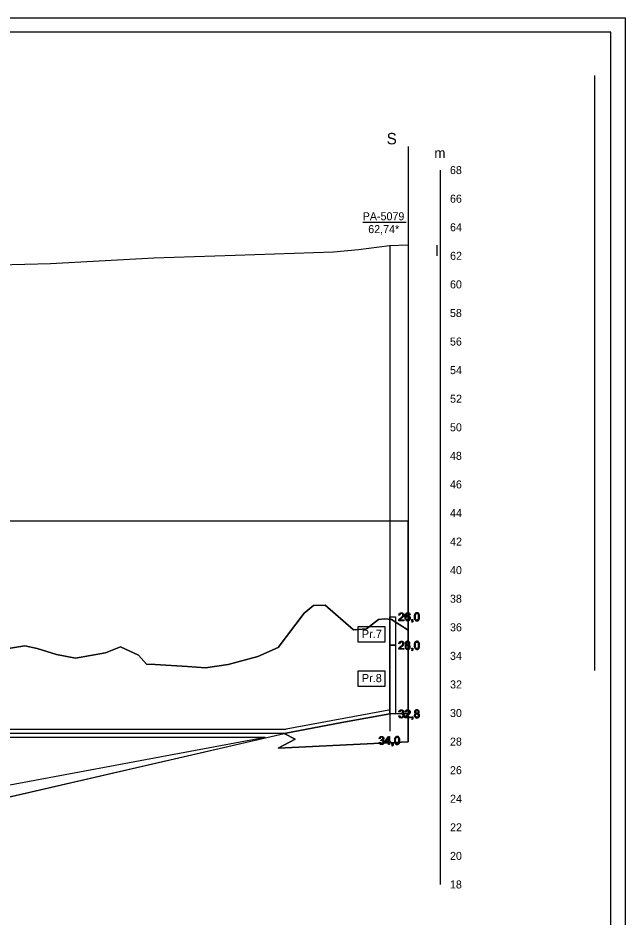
# Model space of a CAD drawing. Extents: x 700746 to 706058, y 6570320 to 6580460.
# Drawn here: x 705472 to 705897, y 6574741 to 6575370 of the extents above; entities that cross this region are included whole.
import ezdxf

# ---------------------------------------------------------------- set-up
doc = ezdxf.new("R2010")
doc.units = 0
for name, color, linetype in [('ABIJOONIS', 7, 'Continuous'), ('GEOLPUNKT', 7, 'Continuous'), ('GEOLPUNKT_proovid', 7, 'Continuous'), ('Lõige', 7, 'Continuous'), ('Lõige vormistus', 7, 'Continuous'), ('Maapind', 7, 'Continuous'), ('PIIR', 7, 'Continuous'), ('Plokid', 7, 'Continuous'), ('Täide', 7, 'Continuous'), ('VEEKOGU', 7, 'Continuous'), ('Veetase', 7, 'Continuous'), ('VORMISTUS', 7, 'Continuous')]:
    doc.layers.add(name, color=color, linetype=linetype)

msp = doc.modelspace()

# ---------------------------------------------------------------- linework, layer by layer
at = {"layer": 'ABIJOONIS'}
msp.add_lwpolyline([(704017.06, 6575370.2), (705897.06, 6575370.2), (705897.06, 6574500.2), (704017.06, 6574500.2), (704017.06, 6575370.2)], dxfattribs=at)
at = {"layer": 'GEOLPUNKT'}
for p, q in [((705713.48, 6575227.4), (705743.92, 6575227.4)), ((705732.33, 6575211.13), (705732.33, 6574949.04)), ((705732.33, 6574949.04), (705732.33, 6574871.13))]:
    msp.add_line(p, q, dxfattribs=at)
at = {"layer": 'GEOLPUNKT_proovid'}
for points in [[(705732.33, 6574951.13), (705736.33, 6574951.13), (705736.33, 6574931.13), (705732.33, 6574931.13)], [(705710.25, 6574944.24), (705728.96, 6574944.24), (705728.96, 6574933.28), (705710.25, 6574933.28)], [(705732.33, 6574931.13), (705736.33, 6574931.13), (705736.33, 6574883.13), (705732.33, 6574883.13)], [(705710.25, 6574913.31), (705728.96, 6574913.31), (705728.96, 6574902.35), (705710.25, 6574902.35)]]:
    msp.add_lwpolyline(points, close=True, dxfattribs=at)
for points in [[(705739.45, 6574952.26), (705738.74, 6574952.33)], [(705746.62, 6574952.55), (705745.94, 6574952.5)], [(705742.31, 6574948.99), (705742.31, 6574948.33), (705738.61, 6574948.33)], [(705739.57, 6574948.99), (705742.31, 6574948.99)], [(705747.91, 6574947.22), (705747.72, 6574947.51)], [(705747.77, 6574948.33), (705747.77, 6574949.11), (705748.55, 6574949.11), (705748.55, 6574948.33)], [(705748.16, 6574948.33), (705747.77, 6574948.33)], [(705739.45, 6574932.26), (705738.74, 6574932.33)], [(705742.31, 6574928.99), (705742.31, 6574928.33), (705738.61, 6574928.33)], [(705739.57, 6574928.99), (705742.31, 6574928.99)], [(705747.91, 6574927.22), (705747.72, 6574927.51)], [(705747.77, 6574928.33), (705747.77, 6574929.11), (705748.55, 6574929.11), (705748.55, 6574928.33)], [(705748.16, 6574928.33), (705747.77, 6574928.33)], [(705738.7, 6574881.81), (705739.39, 6574881.9)], [(705739.46, 6574884.38), (705738.77, 6574884.5)], [(705740.06, 6574882.98), (705740.14, 6574883.59)], [(705743.8, 6574884.26), (705743.09, 6574884.33)], [(705746.66, 6574880.99), (705746.66, 6574880.33), (705742.96, 6574880.33)], [(705743.92, 6574880.99), (705746.66, 6574880.99)], [(705747.91, 6574879.22), (705747.72, 6574879.51)], [(705747.77, 6574880.33), (705747.77, 6574881.11), (705748.55, 6574881.11), (705748.55, 6574880.33)], [(705748.16, 6574880.33), (705747.77, 6574880.33)]]:
    msp.add_lwpolyline(points, dxfattribs=at)
for points in [[(705738.61, 6574948.33), (705738.6, 6574948.58), (705738.69, 6574948.81), (705738.83, 6574949.19), (705739.14, 6574949.55), (705739.45, 6574949.92), (705740.04, 6574950.4), (705740.95, 6574951.15), (705741.27, 6574951.59), (705741.59, 6574952.02), (705741.59, 6574952.41), (705741.59, 6574952.82), (705741.3, 6574953.1), (705741.01, 6574953.38), (705740.54, 6574953.38), (705740.05, 6574953.38), (705739.75, 6574953.08), (705739.45, 6574952.79), (705739.45, 6574952.26)], [(705738.74, 6574952.33), (705738.81, 6574953.12), (705739.28, 6574953.54), (705739.76, 6574953.95), (705740.56, 6574953.95), (705741.36, 6574953.95), (705741.83, 6574953.5), (705742.3, 6574953.06), (705742.3, 6574952.4), (705742.3, 6574952.06), (705742.16, 6574951.74), (705742.03, 6574951.41), (705741.71, 6574951.05), (705741.39, 6574950.69), (705740.65, 6574950.07), (705740.03, 6574949.55), (705739.86, 6574949.36), (705739.68, 6574949.18), (705739.57, 6574948.99)], [(705745.94, 6574952.5), (705745.85, 6574952.91), (705745.68, 6574953.09), (705745.4, 6574953.39), (705744.99, 6574953.39), (705744.66, 6574953.39), (705744.41, 6574953.2), (705744.08, 6574952.97), (705743.9, 6574952.51), (705743.71, 6574952.06), (705743.7, 6574951.22), (705743.95, 6574951.59), (705744.31, 6574951.78), (705744.67, 6574951.96), (705745.06, 6574951.96), (705745.75, 6574951.96), (705746.24, 6574951.46), (705746.72, 6574950.95), (705746.72, 6574950.15), (705746.72, 6574949.62), (705746.49, 6574949.17), (705746.26, 6574948.72), (705745.87, 6574948.48), (705745.47, 6574948.24), (705744.96, 6574948.24), (705744.1, 6574948.24), (705743.56, 6574948.87), (705743.02, 6574949.5), (705743.02, 6574950.95), (705743.02, 6574952.57), (705743.62, 6574953.31), (705744.14, 6574953.95), (705745.03, 6574953.95), (705745.69, 6574953.95), (705746.11, 6574953.58), (705746.54, 6574953.21), (705746.62, 6574952.55)], [(705743.81, 6574950.14), (705743.81, 6574949.79), (705743.96, 6574949.46), (705744.11, 6574949.14), (705744.38, 6574948.97), (705744.65, 6574948.8), (705744.95, 6574948.8), (705745.39, 6574948.8), (705745.7, 6574949.15), (705746.01, 6574949.5), (705746.01, 6574950.11), (705746.01, 6574950.69), (705745.7, 6574951.02), (705745.39, 6574951.36), (705744.92, 6574951.36), (705744.46, 6574951.36), (705744.13, 6574951.02), (705743.81, 6574950.69), (705743.81, 6574950.14)], [(705749.57, 6574951.09), (705749.57, 6574952.08), (705749.78, 6574952.69), (705749.98, 6574953.3), (705750.38, 6574953.62), (705750.78, 6574953.95), (705751.4, 6574953.95), (705751.85, 6574953.95), (705752.19, 6574953.77), (705752.53, 6574953.59), (705752.75, 6574953.25), (705752.97, 6574952.9), (705753.09, 6574952.41), (705753.22, 6574951.92), (705753.22, 6574951.09), (705753.22, 6574950.11), (705753.02, 6574949.5), (705752.82, 6574948.89), (705752.41, 6574948.56), (705752.01, 6574948.24), (705751.4, 6574948.24), (705750.59, 6574948.24), (705750.12, 6574948.81), (705749.57, 6574949.51), (705749.57, 6574951.09)], [(705750.28, 6574951.09), (705750.28, 6574949.71), (705750.6, 6574949.25), (705750.92, 6574948.8), (705751.4, 6574948.8), (705751.87, 6574948.8), (705752.19, 6574949.26), (705752.51, 6574949.71), (705752.51, 6574951.09), (705752.51, 6574952.47), (705752.19, 6574952.93), (705751.87, 6574953.38), (705751.39, 6574953.38), (705750.92, 6574953.38), (705750.63, 6574952.98), (705750.28, 6574952.47), (705750.28, 6574951.09)], [(705747.72, 6574947.51), (705747.94, 6574947.61), (705748.04, 6574947.8), (705748.15, 6574947.98), (705748.16, 6574948.33)], [(705748.55, 6574948.33), (705748.55, 6574947.9), (705748.4, 6574947.63), (705748.25, 6574947.36), (705747.91, 6574947.22)], [(705738.61, 6574928.33), (705738.6, 6574928.58), (705738.69, 6574928.81), (705738.83, 6574929.19), (705739.14, 6574929.55), (705739.45, 6574929.92), (705740.04, 6574930.4), (705740.95, 6574931.15), (705741.27, 6574931.59), (705741.59, 6574932.02), (705741.59, 6574932.41), (705741.59, 6574932.82), (705741.3, 6574933.1), (705741.01, 6574933.38), (705740.54, 6574933.38), (705740.05, 6574933.38), (705739.75, 6574933.08), (705739.45, 6574932.79), (705739.45, 6574932.26)], [(705738.74, 6574932.33), (705738.81, 6574933.12), (705739.28, 6574933.54), (705739.76, 6574933.95), (705740.56, 6574933.95), (705741.36, 6574933.95), (705741.83, 6574933.5), (705742.3, 6574933.06), (705742.3, 6574932.4), (705742.3, 6574932.06), (705742.16, 6574931.74), (705742.03, 6574931.41), (705741.71, 6574931.05), (705741.39, 6574930.69), (705740.65, 6574930.07), (705740.03, 6574929.55), (705739.86, 6574929.36), (705739.68, 6574929.18), (705739.57, 6574928.99)], [(705744.11, 6574931.37), (705743.68, 6574931.52), (705743.47, 6574931.81), (705743.27, 6574932.1), (705743.27, 6574932.51), (705743.27, 6574933.12), (705743.71, 6574933.53), (705744.14, 6574933.95), (705744.87, 6574933.95), (705745.6, 6574933.95), (705746.05, 6574933.53), (705746.5, 6574933.1), (705746.5, 6574932.49), (705746.5, 6574932.1), (705746.29, 6574931.81), (705746.09, 6574931.52), (705745.67, 6574931.37), (705746.19, 6574931.2), (705746.46, 6574930.83), (705746.73, 6574930.45), (705746.73, 6574929.93), (705746.73, 6574929.21), (705746.22, 6574928.72), (705745.71, 6574928.24), (705744.88, 6574928.24), (705744.06, 6574928.24), (705743.55, 6574928.73), (705743.04, 6574929.22), (705743.04, 6574929.95), (705743.04, 6574930.5), (705743.32, 6574930.87), (705743.6, 6574931.23), (705744.11, 6574931.37)], [(705743.98, 6574932.53), (705743.98, 6574932.14), (705744.23, 6574931.88), (705744.48, 6574931.63), (705744.89, 6574931.63), (705745.29, 6574931.63), (705745.54, 6574931.88), (705745.79, 6574932.13), (705745.79, 6574932.49), (705745.79, 6574932.87), (705745.53, 6574933.13), (705745.27, 6574933.39), (705744.88, 6574933.39), (705744.49, 6574933.39), (705744.23, 6574933.14), (705743.98, 6574932.88), (705743.98, 6574932.53)], [(705749.57, 6574931.09), (705749.57, 6574932.08), (705749.78, 6574932.69), (705749.98, 6574933.3), (705750.38, 6574933.62), (705750.78, 6574933.95), (705751.4, 6574933.95), (705751.85, 6574933.95), (705752.19, 6574933.77), (705752.53, 6574933.59), (705752.75, 6574933.25), (705752.97, 6574932.9), (705753.09, 6574932.41), (705753.22, 6574931.92), (705753.22, 6574931.09), (705753.22, 6574930.11), (705753.02, 6574929.5), (705752.82, 6574928.89), (705752.41, 6574928.56), (705752.01, 6574928.24), (705751.4, 6574928.24), (705750.59, 6574928.24), (705750.12, 6574928.81), (705749.57, 6574929.51), (705749.57, 6574931.09)], [(705750.28, 6574931.09), (705750.28, 6574929.71), (705750.6, 6574929.25), (705750.92, 6574928.8), (705751.4, 6574928.8), (705751.87, 6574928.8), (705752.19, 6574929.26), (705752.51, 6574929.71), (705752.51, 6574931.09), (705752.51, 6574932.47), (705752.19, 6574932.93), (705751.87, 6574933.38), (705751.39, 6574933.38), (705750.92, 6574933.38), (705750.63, 6574932.98), (705750.28, 6574932.47), (705750.28, 6574931.09)], [(705743.75, 6574929.95), (705743.75, 6574929.65), (705743.89, 6574929.38), (705744.02, 6574929.1), (705744.3, 6574928.95), (705744.57, 6574928.8), (705744.89, 6574928.8), (705745.38, 6574928.8), (705745.7, 6574929.12), (705746.02, 6574929.43), (705746.02, 6574929.92), (705746.02, 6574930.42), (705745.69, 6574930.74), (705745.36, 6574931.07), (705744.87, 6574931.07), (705744.38, 6574931.07), (705744.07, 6574930.75), (705743.75, 6574930.43), (705743.75, 6574929.95)], [(705747.72, 6574927.51), (705747.94, 6574927.61), (705748.04, 6574927.8), (705748.15, 6574927.98), (705748.16, 6574928.33)], [(705748.55, 6574928.33), (705748.55, 6574927.9), (705748.4, 6574927.63), (705748.25, 6574927.36), (705747.91, 6574927.22)], [(705738.77, 6574884.5), (705738.9, 6574885.19), (705739.35, 6574885.57), (705739.79, 6574885.95), (705740.46, 6574885.95), (705740.92, 6574885.95), (705741.3, 6574885.75), (705741.69, 6574885.56), (705741.89, 6574885.22), (705742.1, 6574884.88), (705742.1, 6574884.5), (705742.1, 6574884.14), (705741.9, 6574883.84), (705741.71, 6574883.54), (705741.33, 6574883.36), (705741.82, 6574883.25), (705742.1, 6574882.89), (705742.37, 6574882.53), (705742.37, 6574881.99), (705742.37, 6574881.25), (705741.84, 6574880.74), (705741.3, 6574880.24), (705740.48, 6574880.24), (705739.75, 6574880.24), (705739.26, 6574880.67), (705738.77, 6574881.11), (705738.7, 6574881.81)], [(705739.39, 6574881.9), (705739.51, 6574881.32), (705739.79, 6574881.06), (705740.08, 6574880.8), (705740.49, 6574880.8), (705740.97, 6574880.8), (705741.31, 6574881.14), (705741.64, 6574881.47), (705741.64, 6574881.97), (705741.64, 6574882.45), (705741.33, 6574882.75), (705741.02, 6574883.06), (705740.54, 6574883.06), (705740.35, 6574883.06), (705740.06, 6574882.98)], [(705740.14, 6574883.59), (705740.2, 6574883.58), (705740.25, 6574883.58), (705740.69, 6574883.58), (705741.04, 6574883.81), (705741.39, 6574884.04), (705741.39, 6574884.51), (705741.39, 6574884.89), (705741.13, 6574885.14), (705740.88, 6574885.39), (705740.47, 6574885.39), (705740.07, 6574885.39), (705739.8, 6574885.13), (705739.54, 6574884.88), (705739.46, 6574884.38)], [(705742.96, 6574880.33), (705742.95, 6574880.58), (705743.04, 6574880.81), (705743.18, 6574881.19), (705743.49, 6574881.55), (705743.8, 6574881.92), (705744.39, 6574882.4), (705745.3, 6574883.15), (705745.62, 6574883.59), (705745.94, 6574884.02), (705745.94, 6574884.41), (705745.94, 6574884.82), (705745.65, 6574885.1), (705745.36, 6574885.38), (705744.89, 6574885.38), (705744.39, 6574885.38), (705744.1, 6574885.08), (705743.8, 6574884.79), (705743.8, 6574884.26)], [(705743.09, 6574884.33), (705743.16, 6574885.12), (705743.63, 6574885.54), (705744.11, 6574885.95), (705744.91, 6574885.95), (705745.71, 6574885.95), (705746.18, 6574885.5), (705746.65, 6574885.06), (705746.65, 6574884.4), (705746.65, 6574884.06), (705746.51, 6574883.74), (705746.38, 6574883.41), (705746.06, 6574883.05), (705745.74, 6574882.69), (705745, 6574882.07), (705744.38, 6574881.55), (705744.21, 6574881.36), (705744.03, 6574881.18), (705743.92, 6574880.99)], [(705750.63, 6574883.37), (705750.2, 6574883.52), (705750, 6574883.81), (705749.79, 6574884.1), (705749.79, 6574884.51), (705749.79, 6574885.12), (705750.23, 6574885.53), (705750.67, 6574885.95), (705751.39, 6574885.95), (705752.13, 6574885.95), (705752.57, 6574885.53), (705753.02, 6574885.1), (705753.02, 6574884.49), (705753.02, 6574884.1), (705752.81, 6574883.81), (705752.61, 6574883.52), (705752.19, 6574883.37), (705752.71, 6574883.2), (705752.98, 6574882.83), (705753.25, 6574882.45), (705753.25, 6574881.93), (705753.25, 6574881.21), (705752.74, 6574880.72), (705752.23, 6574880.24), (705751.41, 6574880.24), (705750.58, 6574880.24), (705750.07, 6574880.73), (705749.56, 6574881.22), (705749.56, 6574881.95), (705749.56, 6574882.5), (705749.84, 6574882.87), (705750.12, 6574883.23), (705750.63, 6574883.37)], [(705750.27, 6574881.95), (705750.27, 6574881.65), (705750.41, 6574881.38), (705750.55, 6574881.1), (705750.82, 6574880.95), (705751.1, 6574880.8), (705751.41, 6574880.8), (705751.9, 6574880.8), (705752.22, 6574881.12), (705752.54, 6574881.43), (705752.54, 6574881.92), (705752.54, 6574882.42), (705752.21, 6574882.74), (705751.89, 6574883.07), (705751.39, 6574883.07), (705750.9, 6574883.07), (705750.59, 6574882.75), (705750.27, 6574882.43), (705750.27, 6574881.95)], [(705750.5, 6574884.53), (705750.5, 6574884.14), (705750.75, 6574883.88), (705751, 6574883.63), (705751.41, 6574883.63), (705751.81, 6574883.63), (705752.06, 6574883.88), (705752.31, 6574884.13), (705752.31, 6574884.49), (705752.31, 6574884.87), (705752.05, 6574885.13), (705751.79, 6574885.39), (705751.4, 6574885.39), (705751.01, 6574885.39), (705750.75, 6574885.14), (705750.5, 6574884.88), (705750.5, 6574884.53)], [(705747.72, 6574879.51), (705747.94, 6574879.61), (705748.04, 6574879.8), (705748.15, 6574879.98), (705748.16, 6574880.33)], [(705748.55, 6574880.33), (705748.55, 6574879.9), (705748.4, 6574879.63), (705748.25, 6574879.36), (705747.91, 6574879.22)]]:
    msp.add_open_spline(points, degree=3, dxfattribs=at)
at = {"layer": 'Lõige'}
msp.add_lwpolyline([(705432.36, 6575196.11), (705458.64, 6575197.47), (705494.75, 6575198.38), (705567.24, 6575202.44), (705624.05, 6575204.19), (705693.03, 6575206.5), (705710.43, 6575208.05), (705732.19, 6575211), (705745.12, 6575211.32)], dxfattribs=at)
at = {"layer": 'Lõige vormistus'}
msp.add_line((705767.59, 6575263.73), (705767.59, 6574763.73), dxfattribs=at)
at = {"layer": 'Maapind'}
msp.add_line((705450.07, 6574821.41), (705658.33, 6574869.28), dxfattribs=at)
for points in [[(705745.34, 6575018.64), (705745.34, 6574863.57)], [(705745.34, 6574863.57), (705654.31, 6574859.08), (705666.01, 6574865.46), (705658.33, 6574869.28)]]:
    msp.add_lwpolyline(points, dxfattribs=at)
at = {"layer": 'PIIR'}
msp.add_line((705732.33, 6574883.13), (705660.11, 6574869.63), dxfattribs=at)
msp.add_lwpolyline([(704401.55, 6574869.63), (705660.11, 6574869.63)], dxfattribs=at)
at = {"layer": 'Plokid'}
for p, q in [((705875.8, 6575330.04), (705875.8, 6574913.38)), ((705745.34, 6575280.23), (705745.34, 6574863.57)), ((705731.82, 6574885.83), (705659.86, 6574872.38)), ((704401.55, 6574872.38), (705659.86, 6574872.38)), ((704146.26, 6574866.83), (705645.04, 6574866.83))]:
    msp.add_line(p, q, dxfattribs=at)
for points in [[(705745.34, 6574941.75), (705733.6, 6574949.22), (705728.99, 6574949.73), (705724.38, 6574949.1), (705716.13, 6574942.7), (705706.93, 6574941.89), (705687.04, 6574959.18), (705678.92, 6574958.97), (705672.42, 6574953.68), (705654.26, 6574929.51), (705639.94, 6574923.21), (705619.21, 6574917.66), (705603.39, 6574915.24), (705590.67, 6574916.4), (705568.17, 6574917.7), (705562.04, 6574917.84), (705556.47, 6574924.24), (705543.8, 6574929.98), (705533.34, 6574925.92), (705512.3, 6574922.08), (705499.04, 6574924.77), (705485.56, 6574928.93), (705476.91, 6574930.82), (705462.41, 6574928.41)], [(705745.3, 6574883.37), (705732.24, 6574883.13), (705732.24, 6574883.13), (705732.24, 6574883.13)], [(704399.9, 6574813.93), (704646.39, 6574838.03), (704915.95, 6574846.43), (705118.38, 6574796.88), (705170.55, 6574795.33), (705409.93, 6574822.93), (705409.93, 6574822.93), (705409.93, 6574822.93), (705645.04, 6574866.83)]]:
    msp.add_lwpolyline(points, dxfattribs=at)
at = {"layer": 'Täide'}
for p, q in [((705745.34, 6574863.57), (705745.34, 6574883.37)), ((705658.33, 6574869.28), (705698.71, 6574877.12)), ((705450.07, 6574821.41), (705658.33, 6574869.28))]:
    msp.add_line(p, q, dxfattribs=at)
for points in [[(705450.07, 6574821.41), (705658.33, 6574869.28), (705698.71, 6574877.12), (705732.33, 6574883.13), (705745.34, 6574883.37), (705745.34, 6574941.75), (705733.6, 6574949.22), (705728.99, 6574949.73), (705724.38, 6574949.1), (705716.13, 6574942.7), (705706.93, 6574941.89), (705687.04, 6574959.18), (705678.92, 6574958.97), (705672.33, 6574953.57), (705654.26, 6574929.51), (705639.94, 6574923.21), (705619.21, 6574917.66), (705603.39, 6574915.24), (705590.67, 6574916.4), (705568.17, 6574917.7), (705562.04, 6574917.84), (705556.47, 6574924.24), (705543.8, 6574929.98), (705533.34, 6574925.92), (705512.3, 6574922.08), (705499.04, 6574924.77), (705485.56, 6574928.93), (705476.91, 6574930.82), (705462.41, 6574928.41)], [(705698.71, 6574877.12), (705732.33, 6574883.13), (705745.34, 6574883.37), (705745.34, 6574941.75), (705733.6, 6574949.22), (705728.99, 6574949.73), (705724.38, 6574949.1), (705716.13, 6574942.7), (705706.93, 6574941.89), (705687.04, 6574959.18), (705678.92, 6574958.97), (705672.33, 6574953.57), (705654.26, 6574929.51), (705639.94, 6574923.21), (705619.21, 6574917.66), (705603.39, 6574915.24), (705590.67, 6574916.4), (705568.17, 6574917.7), (705562.04, 6574917.84), (705556.47, 6574924.24), (705543.8, 6574929.98), (705533.34, 6574925.92), (705512.3, 6574922.08), (705499.04, 6574924.77), (705485.56, 6574928.93), (705476.91, 6574930.82), (705462.41, 6574928.41)], [(705745.34, 6574883.37), (705732.33, 6574883.13), (705698.71, 6574877.12), (705658.33, 6574869.28)], [(705658.33, 6574869.28), (705666.01, 6574865.46), (705654.31, 6574859.08), (705745.34, 6574863.57)]]:
    msp.add_lwpolyline(points, dxfattribs=at)
at = {"layer": 'VEEKOGU'}
for p, q in [((705745.34, 6575018.05), (705325.88, 6575017.92)), ((705745.34, 6574941.75), (705745.34, 6575018.05)), ((705716.13, 6574942.7), (705724.38, 6574949.1)), ((705512.3, 6574922.08), (705533.34, 6574925.92)), ((705533.34, 6574925.92), (705543.8, 6574929.98)), ((705543.8, 6574929.98), (705556.47, 6574924.24)), ((705639.94, 6574923.21), (705654.26, 6574929.51))]:
    msp.add_line(p, q, dxfattribs=at)
for points in [[(705443.11, 6574957.68), (705453.1, 6574942.63), (705462.41, 6574928.41), (705476.91, 6574930.82), (705485.56, 6574928.93)], [(705654.26, 6574929.51), (705672.33, 6574953.57), (705678.92, 6574958.97), (705687.04, 6574959.18), (705706.93, 6574941.89), (705716.13, 6574942.7)], [(705724.38, 6574949.1), (705728.99, 6574949.73), (705733.6, 6574949.22), (705745.34, 6574941.75)], [(705485.56, 6574928.93), (705499.04, 6574924.77), (705512.3, 6574922.08)], [(705556.47, 6574924.24), (705562.04, 6574917.84), (705568.17, 6574917.7), (705590.67, 6574916.4)], [(705590.67, 6574916.4), (705603.39, 6574915.24), (705619.21, 6574917.66), (705639.94, 6574923.21)]]:
    msp.add_lwpolyline(points, dxfattribs=at)
at = {"layer": 'Veetase'}
msp.add_line((705765.59, 6575203.73), (705765.59, 6575211.13), dxfattribs=at)
at = {"layer": 'VORMISTUS'}
msp.add_lwpolyline([(704057.06, 6574510.2), (705887.06, 6574510.2), (705887.06, 6575360.2), (704057.06, 6575360.2)], close=True, dxfattribs=at)
for points in [[(705724.85, 6574863.2), (705725.53, 6574863.29)], [(705725.6, 6574865.76), (705724.91, 6574865.89)], [(705726.2, 6574864.37), (705726.28, 6574864.97)], [(705731.39, 6574861.72), (705731.39, 6574863.06), (705728.96, 6574863.06), (705728.96, 6574863.69), (705731.52, 6574867.32), (705732.08, 6574867.32), (705732.08, 6574863.69), (705732.84, 6574863.69), (705732.84, 6574863.06), (705732.08, 6574863.06), (705732.08, 6574861.72), (705731.39, 6574861.72)], [(705731.39, 6574863.69), (705731.39, 6574866.22), (705729.64, 6574863.69), (705731.39, 6574863.69)], [(705734.06, 6574860.61), (705733.86, 6574860.9)], [(705733.91, 6574861.72), (705733.91, 6574862.5), (705734.69, 6574862.5), (705734.69, 6574861.72)], [(705734.3, 6574861.72), (705733.91, 6574861.72)]]:
    msp.add_lwpolyline(points, dxfattribs=at)
for points in [[(705724.91, 6574865.89), (705725.04, 6574866.58), (705725.49, 6574866.96), (705725.93, 6574867.34), (705726.6, 6574867.34), (705727.06, 6574867.34), (705727.44, 6574867.14), (705727.83, 6574866.95), (705728.03, 6574866.61), (705728.24, 6574866.27), (705728.24, 6574865.89), (705728.24, 6574865.52), (705728.04, 6574865.23), (705727.85, 6574864.93), (705727.47, 6574864.75), (705727.96, 6574864.64), (705728.24, 6574864.28), (705728.51, 6574863.92), (705728.51, 6574863.38), (705728.51, 6574862.64), (705727.98, 6574862.13), (705727.44, 6574861.62), (705726.63, 6574861.62), (705725.89, 6574861.62), (705725.4, 6574862.06), (705724.91, 6574862.5), (705724.85, 6574863.2)], [(705725.53, 6574863.29), (705725.65, 6574862.71), (705725.93, 6574862.45), (705726.22, 6574862.19), (705726.63, 6574862.19), (705727.12, 6574862.19), (705727.45, 6574862.53), (705727.78, 6574862.86), (705727.78, 6574863.36), (705727.78, 6574863.83), (705727.47, 6574864.14), (705727.16, 6574864.45), (705726.69, 6574864.45), (705726.49, 6574864.45), (705726.2, 6574864.37)], [(705726.28, 6574864.97), (705726.35, 6574864.97), (705726.39, 6574864.97), (705726.83, 6574864.97), (705727.18, 6574865.2), (705727.53, 6574865.42), (705727.53, 6574865.9), (705727.53, 6574866.28), (705727.27, 6574866.53), (705727.02, 6574866.78), (705726.61, 6574866.78), (705726.21, 6574866.78), (705725.94, 6574866.52), (705725.68, 6574866.27), (705725.6, 6574865.76)], [(705735.71, 6574864.48), (705735.71, 6574865.47), (705735.92, 6574866.08), (705736.12, 6574866.68), (705736.52, 6574867.01), (705736.93, 6574867.34), (705737.54, 6574867.34), (705737.99, 6574867.34), (705738.33, 6574867.16), (705738.67, 6574866.98), (705738.89, 6574866.63), (705739.11, 6574866.29), (705739.24, 6574865.8), (705739.36, 6574865.31), (705739.36, 6574864.48), (705739.36, 6574863.49), (705739.16, 6574862.89), (705738.96, 6574862.28), (705738.55, 6574861.95), (705738.15, 6574861.62), (705737.54, 6574861.62), (705736.73, 6574861.62), (705736.27, 6574862.2), (705735.71, 6574862.9), (705735.71, 6574864.48)], [(705736.42, 6574864.48), (705736.42, 6574863.1), (705736.74, 6574862.64), (705737.06, 6574862.19), (705737.54, 6574862.19), (705738.01, 6574862.19), (705738.33, 6574862.64), (705738.65, 6574863.1), (705738.65, 6574864.48), (705738.65, 6574865.86), (705738.33, 6574866.32), (705738.01, 6574866.77), (705737.53, 6574866.77), (705737.06, 6574866.77), (705736.77, 6574866.37), (705736.42, 6574865.86), (705736.42, 6574864.48)], [(705733.86, 6574860.9), (705734.08, 6574861), (705734.19, 6574861.18), (705734.29, 6574861.37), (705734.3, 6574861.72)], [(705734.69, 6574861.72), (705734.69, 6574861.29), (705734.54, 6574861.02), (705734.39, 6574860.75), (705734.06, 6574860.61)]]:
    msp.add_open_spline(points, degree=3, dxfattribs=at)

# ---------------------------------------------------------------- texts
at = {"layer": 'GEOLPUNKT'}
for s, p in [('PA-5079', (705713.42, 6575228.61)), ('62,74*', (705717.29, 6575219.61))]:
    msp.add_text(s, height=5.6, dxfattribs=at).set_placement(p)
at = {"layer": 'GEOLPUNKT_proovid'}
for s, height, p in [('26,0', 5.6, (705738.38, 6574948.33)), ('Pr.7', 5.7, (705712.82, 6574936.26)), ('28,0', 5.6, (705738.38, 6574928.33)), ('Pr.8', 5.7, (705712.82, 6574905.33)), ('32,8', 5.6, (705738.38, 6574880.33))]:
    msp.add_text(s, height=height, dxfattribs=at).set_placement(p)
at = {"layer": 'Lõige vormistus'}
for s, height, p in [('S', 8, (705730.18, 6575281.76)), ('m', 7, (705763.56, 6575272.23)), ('68', 5.6, (705774.5, 6575260.93)), ('66', 5.6, (705774.51, 6575240.93)), ('64', 5.6, (705774.54, 6575220.93)), ('62', 5.6, (705774.57, 6575200.93)), ('60', 5.6, (705774.53, 6575180.93)), ('58', 5.6, (705774.5, 6575160.93)), ('56', 5.6, (705774.51, 6575140.93)), ('54', 5.6, (705774.54, 6575120.93)), ('52', 5.6, (705774.57, 6575100.93)), ('50', 5.6, (705774.53, 6575080.93)), ('48', 5.6, (705774.5, 6575060.93)), ('46', 5.6, (705774.51, 6575040.93)), ('44', 5.6, (705774.54, 6575020.93)), ('42', 5.6, (705774.57, 6575000.93)), ('40', 5.6, (705774.53, 6574980.93)), ('38', 5.6, (705774.5, 6574960.93)), ('36', 5.6, (705774.51, 6574940.93)), ('34', 5.6, (705774.54, 6574920.93)), ('32', 5.6, (705774.57, 6574900.93)), ('30', 5.6, (705774.53, 6574880.93)), ('28', 5.6, (705774.5, 6574860.93)), ('26', 5.6, (705774.51, 6574840.93)), ('24', 5.6, (705774.54, 6574820.93)), ('22', 5.6, (705774.57, 6574800.93)), ('20', 5.6, (705774.53, 6574780.93)), ('18', 5.6, (705774.5, 6574760.93))]:
    msp.add_text(s, height=height, dxfattribs=at).set_placement(p)
at = {"layer": 'VORMISTUS'}
msp.add_text('34,0', height=5.6, dxfattribs=at).set_placement((705724.52, 6574861.72))

doc.saveas('drawing.dxf')
